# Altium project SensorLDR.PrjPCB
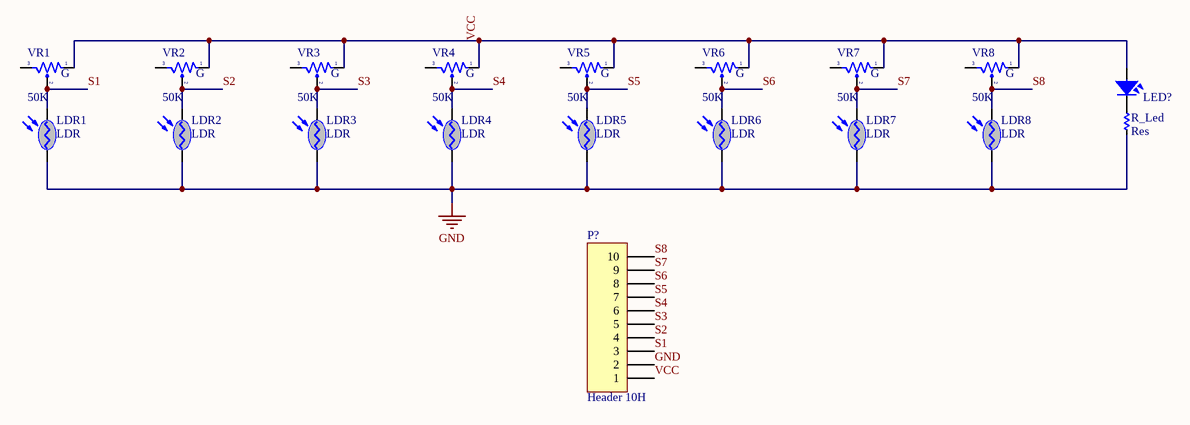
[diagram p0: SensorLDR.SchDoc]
1 sheet, 19 parts. Net scope: global (net labels, ports and power ports of the same name join across sheets).
Board file: SensorLDR_PCB.PcbDoc

## Sheet SensorLDR.SchDoc
size A

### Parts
LDR1  LDR  [CDS]
LDR2  LDR  [CDS]
LDR3  LDR  [CDS]
LDR4  LDR  [CDS]
LDR5  LDR  [CDS]
LDR6  LDR  [CDS]
LDR7  LDR  [CDS]
LDR8  LDR  [CDS]
LED?  LED  [LED-3MM-YELLOW]  (value not drawn)
P?  Header 10H  [HDR1X10H]
R_Led  Res  [RES-1/2W]
VR1  50K  [VR-S2]
VR2  50K  [VR-S2]
VR3  50K  [VR-S2]
VR4  50K  [VR-S2]
VR5  50K  [VR-S2]
VR6  50K  [VR-S2]
VR7  50K  [VR-S2]
VR8  50K  [VR-S2]

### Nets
GND: LDR1.1(A) LDR2.1(A) LDR3.1(A) LDR4.1(A) LDR5.1(A) LDR6.1(A) LDR7.1(A) LDR8.1(A) P?.2 R_Led.2
S1: LDR1.2(K) P?.3 VR1.2
S2: LDR2.2(K) P?.4 VR2.2
S3: LDR3.2(K) P?.5 VR3.2
S4: LDR4.2(K) P?.6 VR4.2
S5: LDR5.2(K) P?.7 VR5.2
S6: LDR6.2(K) P?.8 VR6.2
S7: LDR7.2(K) P?.9 VR7.2
S8: LDR8.2(K) P?.10 VR8.2
VCC: LED?.1 P?.1 VR1.1 VR2.1 VR3.1 VR4.1 VR5.1 VR6.1 VR7.1 VR8.1
NetLED?_2: LED?.2 R_Led.1

Not connected (* = marked no-connect by the designer): VR1 3; VR2 3; VR3 3; VR4 3; VR5 3; VR6 3; VR7 3; VR8 3

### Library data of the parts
LDR1-LDR8 = LDR: Quang Tro
LED? = LED: LED Single colour Green and Red; Value: LED 3 ly Single Colour
P? = Header 10H: Header, 10-Pin, Right Angle
R_Led = Res: Manufacturer: Generic Components; Class: Passive; SubClass: R
VR1-VR8 = VR-S: Var Resistor; Value: Volume 50k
